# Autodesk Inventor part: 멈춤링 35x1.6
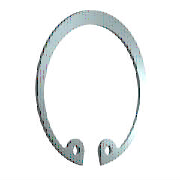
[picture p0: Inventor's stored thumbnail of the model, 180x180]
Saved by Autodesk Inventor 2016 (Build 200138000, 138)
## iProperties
IsCustomPart: 1
Created: 2012-02
Part Number: 멈춤링 35x1.6
Material: 강철, 연강
Description: 리테이닝 링(C형)
Document SubType Name: Modeling
Standard: KS B 1336
Designer: mduedu
Standards Organization: KS
Language: ko-KR
Size Designation: 35x1.6
Categories: <MemberInstance><Categories><Category DisplayName="샤프트 부품" InternalName="7f7aeb1f-a693-4053-b835-cee3144e0d98" Mnemonic="SHFT"><Category DisplayName="써클립" Inter
Density: 1 g/cm^3
Appearance: 파란색 - 벽 페인트 - 광택
Author: mduedu
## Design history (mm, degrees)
sketch "스케치1"
  geometry: L1 (0, 15.113)-(0, -73.177) reference; L2 (-45.5, 0)-(45.5, 0) reference; L3 (-4.964, 1)-(1.502, 1); L4 (0, -2.5)-(-5.307, -2.5); L5 (0, -17.5)-(-8.583, -33.888); L6 (-8.583, -33.888)-(-21.772, -26.981); L7 (-7.377, -31.585)-(-17.631, -26.214); L8 (-5.162, -32.745)-(-6.29, -34.898); L9 (5.162, -32.745)-(6.29, -34.898); C1 r 1.25 at (-7.377, -31.585); C2 r 1.25 at (7.377, -31.585); A1 r 15.875 centre (0, -18.375) between (11.82, -28.972) and (-11.82, -28.972); A2 r 18.5 centre (0, -17.5) between (6.29, -34.898) and (-6.29, -34.898); A3 r 2.5 centre (-7.377, -31.585) between (-5.162, -32.745) and (-8.668, -29.444); A4 r 2.5 centre (-9.959, -27.303) between (-11.82, -28.972) and (-8.668, -29.444); A5 r 2.5 centre (9.959, -27.303) between (8.668, -29.444) and (11.82, -28.972); A6 r 2.5 centre (7.377, -31.585) between (8.668, -29.444) and (5.162, -32.745); 3 further points
  constraints: 15 point on circle, 14 end point, 9 symmetric about line, 8 centre point, 6 tangent, 4 coincident, 4 point on line, 3 perpendicular, 1 parallel, 4 other
  dimensions: "d8" = 0.875 distance of A1.centre L5.start (= 0.25 x SRB1); "d38" = 3.5 distance between parallel lines of L4 L3 (= SRB1); "d39" = 17.5 distance from line of L5.start L2 (= 0.5 x WD); "d43" = 18.5 radius of A2 (= 0.5 x ND); "d45" = 2.6 distance between parallel lines of L7 L6 (= 0.5 x SRB2); "d46" = 2.5 radius of A4 (= SD5); "d47" = 6.29 distance from line of L1 L8.end (= 0.17 x ND); "d48" = 2.5 diameter of C1 (= SD5); "d49" = 2.5 radius of A3 (= SD5)
extrude "본체" new body sketch "스케치1" distance "d2" = 1.6 (= SD); taper "d3" = 0 deg
workaxis "Work Axis1"
workaxis "Work Axis2"
workplane "Work Plane1"
body "Solid1"
other parameters: "WD" = 35 [user parameter; used in 3 equation terms], "SD" = 1.6 [user parameter; used in 1 equation term], "SRB1" = 3.5 [user parameter; used in 2 equation terms], "ND" = 37 [user parameter; used in 2 equation terms], "SRB2" = 5.2 [user parameter; used in 1 equation term], "SD5" = 2.5 [user parameter; used in 3 equation terms], "d50" = 0, "d51" = 0, "d52" = 0, "d53" = 0, "WDMIN" = 34 [user parameter], "SD6" = 37.8 [user parameter], "WDMAX" = 35 (= WD) [user parameter], "NND" = 35 (= WD) [user parameter]
